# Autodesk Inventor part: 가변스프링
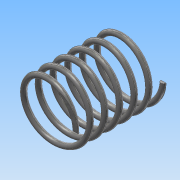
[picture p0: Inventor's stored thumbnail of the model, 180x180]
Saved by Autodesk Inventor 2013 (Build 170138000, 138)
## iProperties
Created: 2016-06
Part Number: 가변스프링
Material: 스테인리스강
Document SubType Name: Modeling
Designer: Administrator
Density: 8.08 g/cm^3
Mass: 84.0961 g
Surface Area: 106.435 cm^2
Volume: 10.4079 cm^3
Author: Administrator
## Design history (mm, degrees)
sketch "스케치1"
  geometry: L1 (0, 0)-(22.5, 0); L2 (22.5, 0)-(22.5, 67.25); L3 (22.5, 67.25)-(0, 67.25); L4 (0, 67.25)-(0, 0); C1 r 2 at (22.5, 0)
  constraints: 8 end point, 2 parallel, 1 centre point, 1 coincident, 1 horizontal, 1 perpendicular
  dimensions: "d1" = 4 diameter of C1; "d3" = 45 diameter of L2 L4; "d4" = 67.25 distance of L3.end L1.start (derived)
feature "코일1" sketch "스케치1" pitch "d5" = 10; turns "d7" = 6; dims "d6" = 67.25 (= d4), "d8" = 0, angle "d9" = 90 deg, angle "d10" = 90 deg, "d11" = 0, "d12" = 0
sketch "스케치2"
  geometry: L1 (0, 30)-(67.25, 30); L2 (67.25, 30)-(67.25, -30); L3 (67.25, -30)-(0, -30); L4 (0, -30)-(0, 30); 4 further points
  constraints: 8 end point, 2 coincident, 2 midpoint, 2 parallel, 1 horizontal, 1 perpendicular
  dimensions: "d13" = 60 distance of L1.end L2.end
extrude "돌출1" sketch "스케치2" stored distance "d16" = 10; taper "d17" = 0 deg
node "솔리드1"
